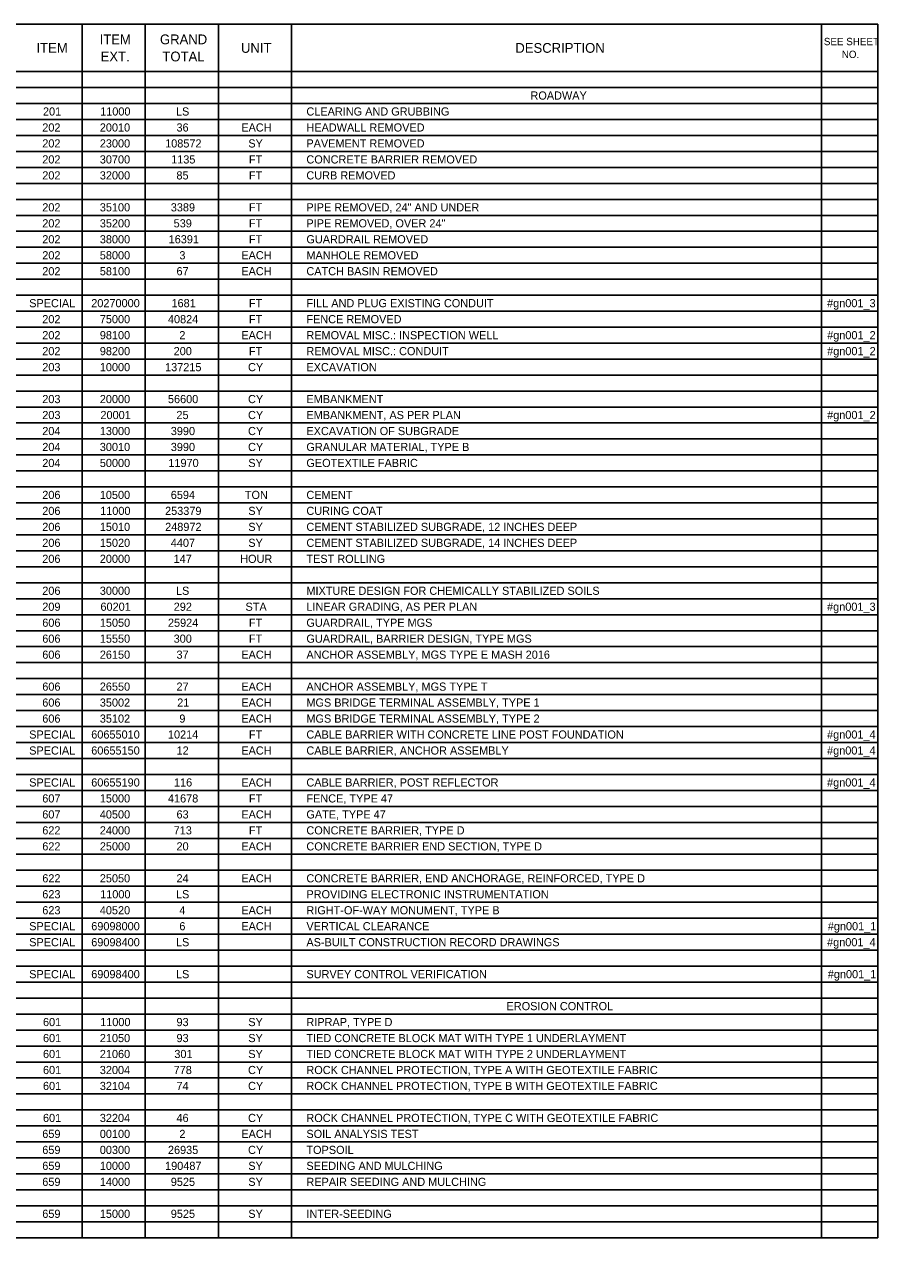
# Model space of a CAD drawing. Extents: x -542 to 295, y -281 to 32.
# Drawn here: x -525.86 to -511.19, y -10.44 to 10.41 of the extents above; entities that cross this region are included whole.
import ezdxf

# ---------------------------------------------------------------- set-up
doc = ezdxf.new("R2010")
doc.units = 0
doc.layers.add('SH_Data', color=7, linetype='Continuous')
doc.layers.add('SH_Text', color=7, linetype='Continuous')

msp = doc.modelspace()

# ---------------------------------------------------------------- linework, layer by layer
at = {"layer": 'SH_Data'}
for p, q in [((-541.706, 10.407), (-511.206, 10.407)), ((-524.87, 10.407), (-524.87, -10.444)), ((-523.785, 10.407), (-523.785, -10.444)), ((-522.529, 10.407), (-522.529, -10.444)), ((-521.273, 10.407), (-521.273, -10.444)), ((-512.174, 10.407), (-512.174, -10.444)), ((-511.206, 10.407), (-511.206, -10.444)), ((-541.706, 9.595), (-511.206, 9.595)), ((-541.706, 9.32), (-511.206, 9.32)), ((-541.706, 9.046), (-511.206, 9.046)), ((-541.706, 8.771), (-511.206, 8.771)), ((-541.706, 8.497), (-511.206, 8.497)), ((-541.706, 8.222), (-511.206, 8.222)), ((-541.706, 7.948), (-511.206, 7.948)), ((-541.706, 7.673), (-511.206, 7.673)), ((-541.706, 7.399), (-511.206, 7.399)), ((-541.706, 7.124), (-511.206, 7.124)), ((-541.706, 6.85), (-511.206, 6.85)), ((-541.706, 6.575), (-511.206, 6.575)), ((-541.706, 6.301), (-511.206, 6.301)), ((-541.706, 6.026), (-511.206, 6.026)), ((-541.706, 5.752), (-511.206, 5.752)), ((-541.706, 5.477), (-511.206, 5.477)), ((-541.706, 5.203), (-511.206, 5.203)), ((-541.706, 4.928), (-511.206, 4.928)), ((-541.706, 4.654), (-511.206, 4.654)), ((-541.706, 4.379), (-511.206, 4.379)), ((-541.706, 4.105), (-511.206, 4.105)), ((-541.706, 3.83), (-511.206, 3.83)), ((-541.706, 3.556), (-511.206, 3.556)), ((-541.706, 3.281), (-511.206, 3.281)), ((-541.706, 3.007), (-511.206, 3.007)), ((-541.706, 2.732), (-511.206, 2.732)), ((-541.706, 2.458), (-511.206, 2.458)), ((-541.706, 2.183), (-511.206, 2.183)), ((-541.706, 1.909), (-511.206, 1.909)), ((-541.706, 1.634), (-511.206, 1.634)), ((-541.706, 1.36), (-511.206, 1.36)), ((-541.706, 1.085), (-511.206, 1.085)), ((-541.706, 0.811), (-511.206, 0.811)), ((-541.706, 0.536), (-511.206, 0.536)), ((-541.706, 0.262), (-511.206, 0.262)), ((-541.706, -0.013), (-511.206, -0.013)), ((-541.706, -0.287), (-511.206, -0.287)), ((-541.706, -0.562), (-511.206, -0.562)), ((-541.706, -0.836), (-511.206, -0.836)), ((-541.706, -1.111), (-511.206, -1.111)), ((-541.706, -1.385), (-511.206, -1.385)), ((-541.706, -1.66), (-511.206, -1.66)), ((-541.706, -1.935), (-511.206, -1.935)), ((-541.706, -2.209), (-511.206, -2.209)), ((-541.706, -2.484), (-511.206, -2.484)), ((-541.706, -2.758), (-511.206, -2.758)), ((-541.706, -3.033), (-511.206, -3.033)), ((-541.706, -3.307), (-511.206, -3.307)), ((-541.706, -3.582), (-511.206, -3.582)), ((-541.706, -3.856), (-511.206, -3.856)), ((-541.706, -4.131), (-511.206, -4.131)), ((-541.706, -4.405), (-511.206, -4.405)), ((-541.706, -4.68), (-511.206, -4.68)), ((-541.706, -4.954), (-511.206, -4.954)), ((-541.706, -5.229), (-511.206, -5.229)), ((-541.706, -5.503), (-511.206, -5.503)), ((-541.706, -5.778), (-511.206, -5.778)), ((-541.706, -6.052), (-511.206, -6.052)), ((-541.706, -6.327), (-511.206, -6.327)), ((-541.706, -6.601), (-511.206, -6.601)), ((-541.706, -6.876), (-511.206, -6.876)), ((-541.706, -7.15), (-511.206, -7.15)), ((-541.706, -7.425), (-511.206, -7.425)), ((-541.706, -7.699), (-511.206, -7.699)), ((-541.706, -7.974), (-511.206, -7.974)), ((-541.706, -8.248), (-511.206, -8.248)), ((-541.706, -8.523), (-511.206, -8.523)), ((-541.706, -8.797), (-511.206, -8.797)), ((-541.706, -9.072), (-511.206, -9.072)), ((-541.706, -9.346), (-511.206, -9.346)), ((-541.706, -9.621), (-511.206, -9.621)), ((-541.706, -9.895), (-511.206, -9.895)), ((-541.706, -10.17), (-511.206, -10.17)), ((-541.706, -10.444), (-511.206, -10.444))]:
    msp.add_line(p, q, dxfattribs=at)

# ---------------------------------------------------------------- texts
at = {"layer": 'SH_Text'}
for s, height, p in [('ITEM', 0.168, (-524.569, 10.064)), ('GRAND ', 0.168, (-523.533, 10.064)), ('ITEM', 0.168, (-525.654, 9.917)), ('UNIT', 0.168, (-522.142, 9.917)), ('DESCRIPTION', 0.168, (-517.43, 9.917)), ('SEE SHEET ', 0.126, (-512.131, 10.048)), ('EXT.', 0.168, (-524.552, 9.77)), ('TOTAL', 0.168, (-523.491, 9.77)), ('NO.', 0.126, (-511.824, 9.828)), ('ROADWAY', 0.14, (-517.17, 9.113)), ('201', 0.14, (-525.542, 8.839)), ('11000', 0.14, (-524.56, 8.839)), ('LS', 0.14, (-523.258, 8.839)), ('CLEARING AND GRUBBING', 0.14, (-521.018, 8.839)), ('202', 0.14, (-525.554, 8.564)), ('20010', 0.14, (-524.566, 8.564)), ('36', 0.14, (-523.249, 8.564)), ('EACH', 0.14, (-522.136, 8.564)), ('HEADWALL REMOVED', 0.14, (-521.018, 8.564)), ('202', 0.14, (-525.554, 8.29)), ('23000', 0.14, (-524.566, 8.29)), ('108572', 0.14, (-523.444, 8.29)), ('SY', 0.14, (-522.016, 8.29)), ('PAVEMENT REMOVED', 0.14, (-521.018, 8.29)), ('202', 0.14, (-525.554, 8.015)), ('30700', 0.14, (-524.566, 8.015)), ('1135', 0.14, (-523.341, 8.015)), ('FT', 0.14, (-522.005, 8.015)), ('CONCRETE BARRIER REMOVED', 0.14, (-521.018, 8.015)), ('202', 0.14, (-525.554, 7.741)), ('32000', 0.14, (-524.566, 7.741)), ('85', 0.14, (-523.25, 7.741)), ('FT', 0.14, (-522.005, 7.741)), ('CURB REMOVED', 0.14, (-521.018, 7.741)), ('202', 0.14, (-525.554, 7.192)), ('35100', 0.14, (-524.566, 7.192)), ('3389', 0.14, (-523.347, 7.192)), ('FT', 0.14, (-522.005, 7.192)), ('PIPE REMOVED, 24" AND UNDER', 0.14, (-521.018, 7.192)), ('202', 0.14, (-525.554, 6.917)), ('35200', 0.14, (-524.566, 6.917)), ('539', 0.14, (-523.298, 6.917)), ('FT', 0.14, (-522.005, 6.917)), ('PIPE REMOVED, OVER 24"', 0.14, (-521.018, 6.917)), ('202', 0.14, (-525.554, 6.643)), ('38000', 0.14, (-524.566, 6.643)), ('16391', 0.14, (-523.384, 6.643)), ('FT', 0.14, (-522.005, 6.643)), ('GUARDRAIL REMOVED', 0.14, (-521.018, 6.643)), ('202', 0.14, (-525.554, 6.368)), ('58000', 0.14, (-524.566, 6.368)), ('3', 0.14, (-523.2, 6.368)), ('EACH', 0.14, (-522.136, 6.368)), ('MANHOLE REMOVED', 0.14, (-521.018, 6.368)), ('202', 0.14, (-525.554, 6.094)), ('58100', 0.14, (-524.566, 6.094)), ('67', 0.14, (-523.249, 6.094)), ('EACH', 0.14, (-522.136, 6.094)), ('CATCH BASIN REMOVED', 0.14, (-521.018, 6.094)), ('SPECIAL', 0.14, (-525.779, 5.545)), ('20270000', 0.14, (-524.713, 5.545)), ('1681', 0.14, (-523.335, 5.545)), ('FT', 0.14, (-522.005, 5.545)), ('FILL AND PLUG EXISTING CONDUIT', 0.14, (-521.018, 5.545)), ('#gn001_3', 0.14, (-512.076, 5.545)), ('202', 0.14, (-525.554, 5.27)), ('75000', 0.14, (-524.566, 5.27)), ('40824', 0.14, (-523.396, 5.27)), ('FT', 0.14, (-522.005, 5.27)), ('FENCE REMOVED', 0.14, (-521.018, 5.27)), ('202', 0.14, (-525.554, 4.995)), ('98100', 0.14, (-524.566, 4.995)), ('2', 0.14, (-523.2, 4.995)), ('EACH', 0.14, (-522.136, 4.995)), ('REMOVAL MISC.: INSPECTION WELL', 0.14, (-521.018, 4.995)), ('#gn001_2', 0.14, (-512.075, 4.995)), ('202', 0.14, (-525.554, 4.721)), ('98200', 0.14, (-524.566, 4.721)), ('200', 0.14, (-523.298, 4.721)), ('FT', 0.14, (-522.005, 4.721)), ('REMOVAL MISC.: CONDUIT', 0.14, (-521.018, 4.721)), ('#gn001_2', 0.14, (-512.075, 4.721)), ('203', 0.14, (-525.554, 4.446)), ('10000', 0.14, (-524.566, 4.446)), ('137215', 0.14, (-523.445, 4.446)), ('CY', 0.14, (-522.02, 4.446)), ('EXCAVATION', 0.14, (-521.018, 4.446)), ('203', 0.14, (-525.554, 3.897)), ('20000', 0.14, (-524.566, 3.897)), ('56600', 0.14, (-523.396, 3.897)), ('CY', 0.14, (-522.02, 3.897)), ('EMBANKMENT', 0.14, (-521.018, 3.897)), ('203', 0.14, (-525.554, 3.623)), ('20001', 0.14, (-524.555, 3.623)), ('25', 0.14, (-523.25, 3.623)), ('CY', 0.14, (-522.02, 3.623)), ('EMBANKMENT, AS PER PLAN', 0.14, (-521.018, 3.623)), ('#gn001_2', 0.14, (-512.075, 3.623)), ('204', 0.14, (-525.554, 3.348)), ('13000', 0.14, (-524.566, 3.348)), ('3990', 0.14, (-523.347, 3.348)), ('CY', 0.14, (-522.02, 3.348)), ('EXCAVATION OF SUBGRADE', 0.14, (-521.018, 3.348)), ('204', 0.14, (-525.554, 3.074)), ('30010', 0.14, (-524.566, 3.074)), ('3990', 0.14, (-523.347, 3.074)), ('CY', 0.14, (-522.02, 3.074)), ('GRANULAR MATERIAL, TYPE B', 0.14, (-521.018, 3.074)), ('204', 0.14, (-525.554, 2.799)), ('50000', 0.14, (-524.566, 2.799)), ('11970', 0.14, (-523.389, 2.799)), ('SY', 0.14, (-522.016, 2.799)), ('GEOTEXTILE FABRIC', 0.14, (-521.018, 2.799)), ('206', 0.14, (-525.554, 2.25)), ('10500', 0.14, (-524.566, 2.25)), ('6594', 0.14, (-523.347, 2.25)), ('TON', 0.14, (-522.075, 2.25)), ('CEMENT', 0.14, (-521.018, 2.25)), ('206', 0.14, (-525.554, 1.976)), ('11000', 0.14, (-524.56, 1.976)), ('253379', 0.14, (-523.445, 1.976)), ('SY', 0.14, (-522.016, 1.976)), ('CURING COAT', 0.14, (-521.018, 1.976)), ('206', 0.14, (-525.554, 1.701)), ('15010', 0.14, (-524.566, 1.701)), ('248972', 0.14, (-523.444, 1.701)), ('SY', 0.14, (-522.016, 1.701)), ('CEMENT STABILIZED SUBGRADE, 12 INCHES DEEP', 0.14, (-521.018, 1.701)), ('206', 0.14, (-525.554, 1.427)), ('15020', 0.14, (-524.566, 1.427)), ('4407', 0.14, (-523.347, 1.427)), ('SY', 0.14, (-522.016, 1.427)), ('CEMENT STABILIZED SUBGRADE, 14 INCHES DEEP', 0.14, (-521.018, 1.427)), ('206', 0.14, (-525.554, 1.152)), ('20000', 0.14, (-524.566, 1.152)), ('147', 0.14, (-523.298, 1.152)), ('HOUR', 0.14, (-522.155, 1.152)), ('TEST ROLLING', 0.14, (-521.018, 1.152)), ('206', 0.14, (-525.554, 0.603)), ('30000', 0.14, (-524.566, 0.603)), ('LS', 0.14, (-523.258, 0.603)), ('MIXTURE DESIGN FOR CHEMICALLY STABILIZED SOILS', 0.14, (-521.018, 0.603)), ('209', 0.14, (-525.554, 0.329)), ('60201', 0.14, (-524.555, 0.329)), ('292', 0.14, (-523.297, 0.329)), ('STA', 0.14, (-522.064, 0.329)), ('LINEAR GRADING, AS PER PLAN', 0.14, (-521.018, 0.329)), ('#gn001_3', 0.14, (-512.076, 0.329)), ('606', 0.14, (-525.554, 0.054)), ('15050', 0.14, (-524.566, 0.054)), ('25924', 0.14, (-523.396, 0.054)), ('FT', 0.14, (-522.005, 0.054)), ('GUARDRAIL, TYPE MGS', 0.14, (-521.018, 0.054)), ('606', 0.14, (-525.554, -0.22)), ('15550', 0.14, (-524.566, -0.22)), ('300', 0.14, (-523.298, -0.22)), ('FT', 0.14, (-522.005, -0.22)), ('GUARDRAIL, BARRIER DESIGN, TYPE MGS', 0.14, (-521.018, -0.22)), ('606', 0.14, (-525.554, -0.495)), ('26150', 0.14, (-524.566, -0.495)), ('37', 0.14, (-523.249, -0.495)), ('EACH', 0.14, (-522.136, -0.495)), ('ANCHOR ASSEMBLY, MGS TYPE E MASH 2016', 0.14, (-521.018, -0.495)), ('606', 0.14, (-525.554, -1.044)), ('26550', 0.14, (-524.566, -1.044)), ('27', 0.14, (-523.249, -1.044)), ('EACH', 0.14, (-522.136, -1.044)), ('ANCHOR ASSEMBLY, MGS TYPE T', 0.14, (-521.018, -1.044)), ('606', 0.14, (-525.554, -1.318)), ('35002', 0.14, (-524.566, -1.318)), ('21', 0.14, (-523.237, -1.318)), ('EACH', 0.14, (-522.136, -1.318)), ('MGS BRIDGE TERMINAL ASSEMBLY, TYPE 1', 0.14, (-521.018, -1.318)), ('606', 0.14, (-525.554, -1.593)), ('35102', 0.14, (-524.566, -1.593)), ('9', 0.14, (-523.2, -1.593)), ('EACH', 0.14, (-522.136, -1.593)), ('MGS BRIDGE TERMINAL ASSEMBLY, TYPE 2', 0.14, (-521.018, -1.593)), ('SPECIAL', 0.14, (-525.779, -1.867)), ('60655010', 0.14, (-524.713, -1.867)), ('10214', 0.14, (-523.396, -1.867)), ('FT', 0.14, (-522.005, -1.867)), ('CABLE BARRIER WITH CONCRETE LINE POST FOUNDATION', 0.14, (-521.018, -1.867)), ('#gn001_4', 0.14, (-512.076, -1.867)), ('SPECIAL', 0.14, (-525.779, -2.142)), ('60655150', 0.14, (-524.713, -2.142)), ('12', 0.14, (-523.248, -2.142)), ('EACH', 0.14, (-522.136, -2.142)), ('CABLE BARRIER, ANCHOR ASSEMBLY', 0.14, (-521.018, -2.142)), ('#gn001_4', 0.14, (-512.076, -2.142)), ('SPECIAL', 0.14, (-525.779, -2.691)), ('60655190', 0.14, (-524.713, -2.691)), ('116', 0.14, (-523.292, -2.691)), ('EACH', 0.14, (-522.136, -2.691)), ('CABLE BARRIER, POST REFLECTOR', 0.14, (-521.018, -2.691)), ('#gn001_4', 0.14, (-512.076, -2.691)), ('607', 0.14, (-525.554, -2.965)), ('15000', 0.14, (-524.566, -2.965)), ('41678', 0.14, (-523.396, -2.965)), ('FT', 0.14, (-522.005, -2.965)), ('FENCE, TYPE 47', 0.14, (-521.018, -2.965)), ('607', 0.14, (-525.554, -3.24)), ('40500', 0.14, (-524.566, -3.24)), ('63', 0.14, (-523.249, -3.24)), ('EACH', 0.14, (-522.136, -3.24)), ('GATE, TYPE 47', 0.14, (-521.018, -3.24)), ('622', 0.14, (-525.554, -3.514)), ('24000', 0.14, (-524.566, -3.514)), ('713', 0.14, (-523.298, -3.514)), ('FT', 0.14, (-522.005, -3.514)), ('CONCRETE BARRIER, TYPE D', 0.14, (-521.018, -3.514)), ('622', 0.14, (-525.554, -3.789)), ('25000', 0.14, (-524.566, -3.789)), ('20', 0.14, (-523.249, -3.789)), ('EACH', 0.14, (-522.136, -3.789)), ('CONCRETE BARRIER END SECTION, TYPE D', 0.14, (-521.018, -3.789)), ('622', 0.14, (-525.554, -4.338)), ('25050', 0.14, (-524.566, -4.338)), ('24', 0.14, (-523.249, -4.338)), ('EACH', 0.14, (-522.136, -4.338)), ('CONCRETE BARRIER, END ANCHORAGE, REINFORCED, TYPE D', 0.14, (-521.018, -4.338)), ('623', 0.14, (-525.554, -4.612)), ('11000', 0.14, (-524.56, -4.612)), ('LS', 0.14, (-523.258, -4.612)), ('PROVIDING ELECTRONIC INSTRUMENTATION', 0.14, (-521.018, -4.612)), ('623', 0.14, (-525.554, -4.887)), ('40520', 0.14, (-524.566, -4.887)), ('4', 0.14, (-523.2, -4.887)), ('EACH', 0.14, (-522.136, -4.887)), ('RIGHT-OF-WAY MONUMENT, TYPE B', 0.14, (-521.018, -4.887)), ('SPECIAL', 0.14, (-525.779, -5.161)), ('69098000', 0.14, (-524.713, -5.161)), ('6', 0.14, (-523.2, -5.161)), ('EACH', 0.14, (-522.136, -5.161)), ('VERTICAL CLEARANCE', 0.14, (-521.018, -5.161)), ('#gn001_1', 0.14, (-512.064, -5.161)), ('SPECIAL', 0.14, (-525.779, -5.436)), ('69098400', 0.14, (-524.713, -5.436)), ('LS', 0.14, (-523.258, -5.436)), ('AS-BUILT CONSTRUCTION RECORD DRAWINGS', 0.14, (-521.018, -5.436)), ('#gn001_4', 0.14, (-512.076, -5.436)), ('SPECIAL', 0.14, (-525.779, -5.985)), ('69098400', 0.14, (-524.713, -5.985)), ('LS', 0.14, (-523.258, -5.985)), ('SURVEY CONTROL VERIFICATION', 0.14, (-521.018, -5.985)), ('#gn001_1', 0.14, (-512.064, -5.985)), ('EROSION CONTROL', 0.14, (-517.581, -6.534)), ('601', 0.14, (-525.542, -6.808)), ('11000', 0.14, (-524.56, -6.808)), ('93', 0.14, (-523.249, -6.808)), ('SY', 0.14, (-522.016, -6.808)), ('RIPRAP, TYPE D', 0.14, (-521.018, -6.808)), ('601', 0.14, (-525.542, -7.083)), ('21050', 0.14, (-524.566, -7.083)), ('93', 0.14, (-523.249, -7.083)), ('SY', 0.14, (-522.016, -7.083)), ('TIED CONCRETE BLOCK MAT WITH TYPE 1 UNDERLAYMENT', 0.14, (-521.018, -7.083)), ('601', 0.14, (-525.542, -7.357)), ('21060', 0.14, (-524.566, -7.357)), ('301', 0.14, (-523.286, -7.357)), ('SY', 0.14, (-522.016, -7.357)), ('TIED CONCRETE BLOCK MAT WITH TYPE 2 UNDERLAYMENT', 0.14, (-521.018, -7.357)), ('601', 0.14, (-525.542, -7.632)), ('32004', 0.14, (-524.566, -7.632)), ('778', 0.14, (-523.298, -7.632)), ('CY', 0.14, (-522.02, -7.632)), ('ROCK CHANNEL PROTECTION, TYPE A WITH GEOTEXTILE FABRIC', 0.14, (-521.018, -7.632)), ('601', 0.14, (-525.542, -7.906)), ('32104', 0.14, (-524.566, -7.906)), ('74', 0.14, (-523.249, -7.906)), ('CY', 0.14, (-522.02, -7.906)), ('ROCK CHANNEL PROTECTION, TYPE B WITH GEOTEXTILE FABRIC', 0.14, (-521.018, -7.906)), ('601', 0.14, (-525.542, -8.456)), ('32204', 0.14, (-524.566, -8.456)), ('46', 0.14, (-523.249, -8.456)), ('CY', 0.14, (-522.02, -8.456)), ('ROCK CHANNEL PROTECTION, TYPE C WITH GEOTEXTILE FABRIC', 0.14, (-521.018, -8.456)), ('659', 0.14, (-525.554, -8.73)), ('00100', 0.14, (-524.566, -8.73)), ('2', 0.14, (-523.2, -8.73)), ('EACH', 0.14, (-522.136, -8.73)), ('SOIL ANALYSIS TEST', 0.14, (-521.018, -8.73)), ('659', 0.14, (-525.554, -9.005)), ('00300', 0.14, (-524.566, -9.005)), ('26935', 0.14, (-523.396, -9.005)), ('CY', 0.14, (-522.02, -9.005)), ('TOPSOIL', 0.14, (-521.018, -9.005)), ('659', 0.14, (-525.554, -9.279)), ('10000', 0.14, (-524.566, -9.279)), ('190487', 0.14, (-523.445, -9.279)), ('SY', 0.14, (-522.016, -9.279)), ('SEEDING AND MULCHING', 0.14, (-521.018, -9.279)), ('659', 0.14, (-525.554, -9.554)), ('14000', 0.14, (-524.566, -9.554)), ('9525', 0.14, (-523.347, -9.554)), ('SY', 0.14, (-522.016, -9.554)), ('REPAIR SEEDING AND MULCHING', 0.14, (-521.018, -9.554)), ('659', 0.14, (-525.554, -10.103)), ('15000', 0.14, (-524.566, -10.103)), ('9525', 0.14, (-523.347, -10.103)), ('SY', 0.14, (-522.016, -10.103)), ('INTER-SEEDING', 0.14, (-521.018, -10.103))]:
    msp.add_text(s, height=height, dxfattribs=at).set_placement(p)

doc.saveas('drawing.dxf')
